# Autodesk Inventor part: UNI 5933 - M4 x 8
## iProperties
Library Location: C:\Programmi\Autodesk\Inventor 6\content
Library: local
SubLibrary: UNI
Family: 0
Member: 60
Member Major Revision: 1
Member Minor Revision: 1
Comments: To add or edit properties for Autodesk Inventor files, use iProperties.
Created: 2004-01
Part Number: UNI 5933 - M4 x 8
Vendor: Autodesk Inc.
Document SubType Name: Modeling
Designer: Lollo
Description: Vite svasata
Standard: UNI 5933 M4 x 8
Alert: To add or edit properties for Autodesk Inventor files, use iProperties.
Control State: 0
Master: False
Checked Out: False
Shininess: 64.0
Length Units: 11269
Angle Units: 11279
Time Units: 11290
Mass Units: 11283
Length Display Precision: 3
Angle Display Precision: 2
Compacted: True
EGR: 1
Density: 0.0
Volumn: 0.0
Area: 0.0
PropertySet Name: Model Information
Author: Lollo
Revision Number: 1
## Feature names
1. Corpo [Revolution]
2. Intaglio [Extrusion]
3. Smusso1 [Chamfer]
